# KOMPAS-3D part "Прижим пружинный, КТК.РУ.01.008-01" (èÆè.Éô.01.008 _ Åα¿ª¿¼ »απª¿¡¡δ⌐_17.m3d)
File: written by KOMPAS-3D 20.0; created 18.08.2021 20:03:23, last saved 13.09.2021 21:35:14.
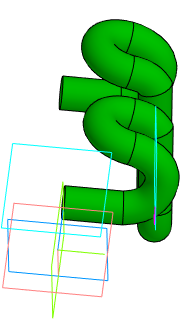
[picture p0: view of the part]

Document properties: Автор: 1; Полное имя файла: E:\Мои документы\КТК\Роликовое устройство\Разработанное\РУ перевернутые болты\прижим пружинный на отправку\КТК.РУ.01.008 _ Прижим пружинный_17.m3d

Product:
- Part/product: Прижим пружинный  | designation КТК.РУ.01.008-01
    Материал: Сталь 60С2Н2А ГОСТ 14959-2016 (density 7680 kg/m3)
    Масса: 0.795288
    source file: ..\КТК.РУ.01.008-01 _ Прижим пружинный_17.cdw, КТК.РУ.01.008 _ Прижим пружинный.cdw

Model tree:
1. Эскиз:1
2. Эскиз:2
3. Элемент по траектории:1
4. Эскиз:3  (with: Элемент по траектории:1)
5. Плоскость через ребро и грань:1  (with: Элемент по траектории:1)
6. Эскиз:4
7. Эскиз:5  (with: Элемент по траектории:1)
8. Элемент по траектории:2
9. Параллельная плоскость:1
10. Эскиз:6
11. Эскиз:7  (with: Элемент по траектории:2)
12. Плоскость через ребро и грань:2  (with: Элемент по траектории:2)
13. Эскиз:8
14. Элемент по траектории:3
15. Элемент выдавливания:2  (with: Элемент по траектории:3, Элемент по траектории:2)
     Расстояние 1 = 0.0104146
16. Плоскость через ребро и грань:3
17. Эскиз:9  (with: Элемент по траектории:3)
18. Эскиз:10  (with: Элемент по траектории:3)
19. Элемент по траектории:4
20. Смещенная плоскость:1
     Расстояние = 57.2
21. Зеркальный массив:3
22. Экземпляр ( 1 )
23. Экземпляр ( 2 )  (with: Элемент по траектории:1, Элемент по траектории:2, Элемент по траектории:3, Элемент по траектории:4)
24. Элемент по сечениям:1  (with: Элемент по траектории:4)  (labels: Сталь 60С2Н2А ГОСТ 14959-2016)

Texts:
  КТК.РУ.01.008-01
